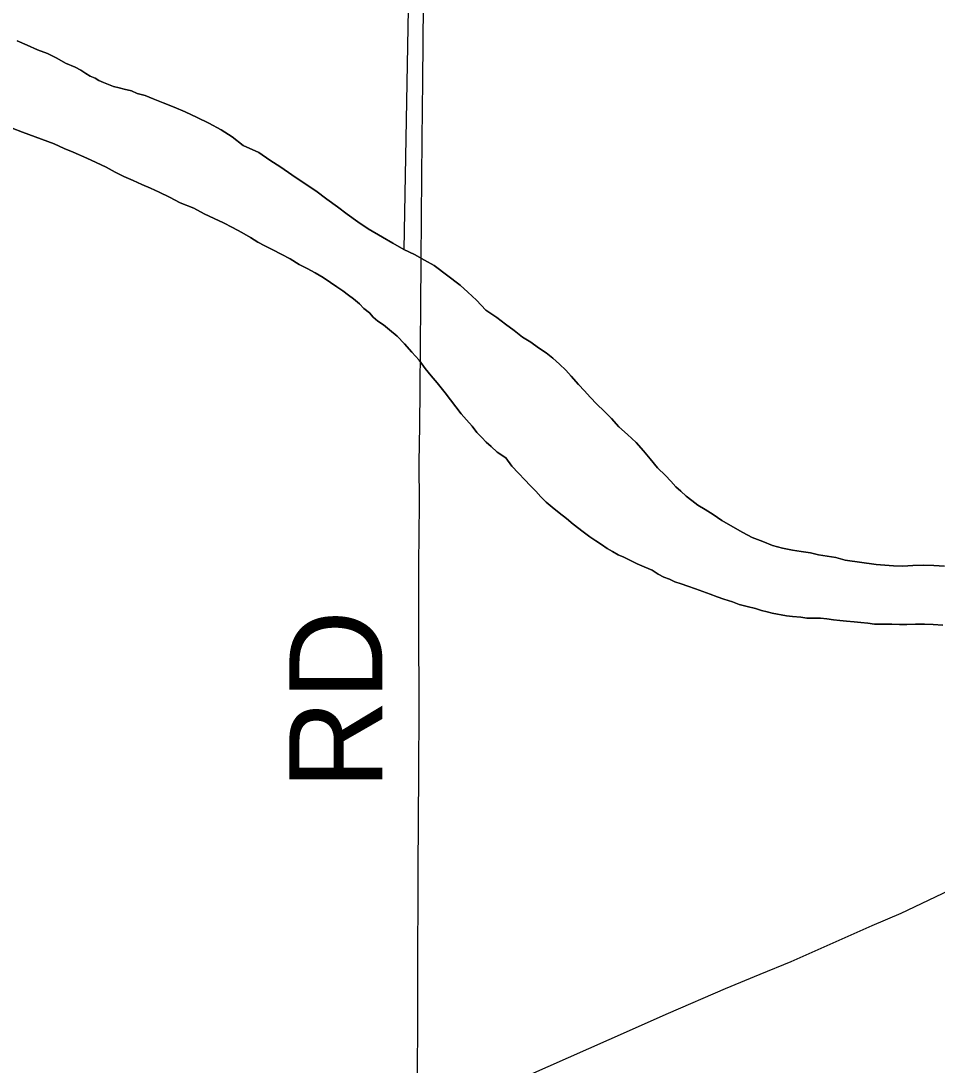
# Model space of a CAD drawing. Extents: x 2.1 to 73.9, y 4 to 26.
# Drawn here: x 45.0013 to 45.2814, y 22.3847 to 22.704 of the extents above; entities that cross this region are included whole.
import ezdxf

# ---------------------------------------------------------------- set-up
doc = ezdxf.new("R2010")
doc.units = 0
for name, color, linetype in [('GM_X_County_Road', 7, 'Continuous'), ('GM_X_County_Road_Text', 7, 'Continuous'), ('GM_X_Major_River', 7, 'Continuous'), ('GM_X_Minor_River', 7, 'Continuous')]:
    doc.layers.add(name, color=color, linetype=linetype)

msp = doc.modelspace()

# ---------------------------------------------------------------- linework, layer by layer
at = {"layer": 'GM_X_County_Road'}
for points in [[(45.12254, 22.36637), (45.12257, 22.36972), (45.12266, 22.41012), (45.12276, 22.44462), (45.12295, 22.47415), (45.12307, 22.49373), (45.12298, 22.51953), (45.12296, 22.53787), (45.12316, 22.5562), (45.12312, 22.56894), (45.12326, 22.58012), (45.12335, 22.59132), (45.12354, 22.61742), (45.12367, 22.63016), (45.12376, 22.64415), (45.12398, 22.66788), (45.12418, 22.6858), (45.1246, 22.73211), (45.12482, 22.75884), (45.12528, 22.79614), (45.12563, 22.81936), (45.12577, 22.84028), (45.12584, 22.84534)], [(45.12254, 22.36637), (45.13764, 22.37322), (45.18113, 22.39248), (45.19932, 22.40055), (45.21674, 22.40804), (45.22738, 22.41243), (45.23683, 22.41638), (45.26157, 22.42732), (45.2704, 22.43114), (45.28304, 22.43711), (45.29225, 22.44163), (45.2967, 22.44381), (45.29941, 22.44531), (45.30667, 22.4495), (45.31849, 22.45638), (45.342, 22.47034), (45.35388, 22.47773), (45.36963, 22.48713), (45.37259, 22.48891)]]:
    msp.add_lwpolyline(points, dxfattribs=at)
at = {"layer": 'GM_X_Major_River'}
for points in [[(45.01228, 22.69262), (45.00945, 22.69399), (45.00642, 22.69518), (45.00321, 22.69656), (45.00019, 22.69794)], [(45.00019, 22.69794), (45.00321, 22.69656), (45.00642, 22.69518), (45.00945, 22.69399), (45.01228, 22.69262)], [(45.28371, 22.53726), (45.28048, 22.5375), (45.27724, 22.53755), (45.27401, 22.53741), (45.27096, 22.53727), (45.26811, 22.53731), (45.26545, 22.53755), (45.26279, 22.53778), (45.25331, 22.53907), (45.25047, 22.53987), (45.24781, 22.5403), (45.24515, 22.54072), (45.24269, 22.54133), (45.23984, 22.54175), (45.23719, 22.54217), (45.23416, 22.54279), (45.23112, 22.5436), (45.2281, 22.54479), (45.22489, 22.54598), (45.22206, 22.54755), (45.21829, 22.5497), (45.21565, 22.55126), (45.21301, 22.55301), (45.21057, 22.55457), (45.20831, 22.55593), (45.20643, 22.55729), (45.20474, 22.55865), (45.20305, 22.5602), (45.20155, 22.56155), (45.20005, 22.56328), (45.19837, 22.56502), (45.19593, 22.56734), (45.19369, 22.57004), (45.19164, 22.57254), (45.1894, 22.57504), (45.18677, 22.57756), (45.18415, 22.57988), (45.18191, 22.58238), (45.17966, 22.5847), (45.17741, 22.58683), (45.17535, 22.58895), (45.17367, 22.59087), (45.1718, 22.5928), (45.16956, 22.59531), (45.16787, 22.59724), (45.166, 22.59898), (45.16394, 22.60091), (45.16187, 22.60246), (45.15961, 22.60402), (45.15717, 22.60577), (45.15472, 22.60733), (45.15209, 22.60927), (45.14946, 22.61121), (45.14683, 22.61334), (45.14344, 22.61549), (45.14063, 22.61857), (45.13801, 22.62108), (45.13557, 22.62321), (45.12768, 22.62923), (45.12466, 22.63079), (45.12164, 22.63255), (45.11844, 22.63412), (45.11504, 22.63608), (45.11184, 22.63784), (45.1075, 22.64038), (45.1043, 22.64252), (45.10111, 22.64485), (45.0981, 22.64718), (45.0949, 22.64951), (45.09152, 22.65203), (45.08794, 22.65437), (45.08418, 22.6569), (45.08079, 22.65923), (45.0774, 22.66137), (45.07402, 22.66371), (45.0693, 22.66587), (45.06592, 22.66859), (45.06253, 22.67073), (45.05875, 22.67269), (45.05517, 22.67446), (45.05158, 22.67623), (45.04818, 22.67761), (45.04478, 22.67899), (45.04175, 22.68018), (45.0393, 22.68117), (45.03683, 22.68178), (45.03513, 22.68257), (45.03286, 22.68317), (45.03135, 22.68358), (45.02964, 22.68398), (45.02813, 22.68458), (45.02662, 22.68517), (45.0251, 22.68577), (45.02398, 22.68654), (45.02246, 22.68714), (45.02114, 22.68792), (45.01964, 22.68889), (45.01794, 22.68987), (45.01492, 22.69106), (45.01228, 22.69262)], [(45.01228, 22.69262), (45.01492, 22.69106), (45.01794, 22.68987), (45.01964, 22.68889), (45.02114, 22.68792), (45.02246, 22.68714), (45.02398, 22.68654), (45.0251, 22.68577), (45.02662, 22.68517), (45.02813, 22.68458), (45.02964, 22.68398), (45.03135, 22.68358), (45.03286, 22.68317), (45.03513, 22.68257), (45.03683, 22.68178), (45.0393, 22.68117), (45.04175, 22.68018), (45.04478, 22.67899), (45.04818, 22.67761), (45.05158, 22.67623), (45.05517, 22.67446), (45.05875, 22.67269), (45.06253, 22.67073), (45.06592, 22.66859), (45.0693, 22.66587), (45.07402, 22.66371), (45.0774, 22.66137), (45.08079, 22.65923), (45.08418, 22.6569), (45.08794, 22.65437), (45.09152, 22.65203), (45.0949, 22.64951), (45.0981, 22.64718), (45.10111, 22.64485), (45.1043, 22.64252), (45.1075, 22.64038), (45.11184, 22.63784), (45.11504, 22.63608), (45.11844, 22.63412), (45.12164, 22.63255), (45.12466, 22.63079), (45.12768, 22.62923), (45.13557, 22.62321), (45.13801, 22.62108), (45.14063, 22.61857), (45.14344, 22.61549), (45.14683, 22.61334), (45.14946, 22.61121), (45.15209, 22.60927), (45.15472, 22.60733), (45.15717, 22.60577), (45.15961, 22.60402), (45.16187, 22.60246), (45.16394, 22.60091), (45.166, 22.59898), (45.16787, 22.59724), (45.16956, 22.59531), (45.1718, 22.5928), (45.17367, 22.59087), (45.17535, 22.58895), (45.17741, 22.58683), (45.17966, 22.5847), (45.18191, 22.58238), (45.18415, 22.57988), (45.18677, 22.57756), (45.1894, 22.57504), (45.19164, 22.57254), (45.19369, 22.57004), (45.19593, 22.56734), (45.19837, 22.56502), (45.20005, 22.56328), (45.20155, 22.56155), (45.20305, 22.5602), (45.20474, 22.55865), (45.20643, 22.55729), (45.20831, 22.55593), (45.21057, 22.55457), (45.21301, 22.55301), (45.21565, 22.55126), (45.21829, 22.5497), (45.22206, 22.54755), (45.22489, 22.54598), (45.2281, 22.54479), (45.23112, 22.5436), (45.23416, 22.54279), (45.23719, 22.54217), (45.23984, 22.54175), (45.24269, 22.54133), (45.24515, 22.54072), (45.24781, 22.5403), (45.25047, 22.53987), (45.25331, 22.53907), (45.26279, 22.53778), (45.26545, 22.53755), (45.26811, 22.53731), (45.27096, 22.53727), (45.27401, 22.53741), (45.27724, 22.53755), (45.28048, 22.5375), (45.28371, 22.53726)], [(44.99863, 22.67118), (45.00184, 22.66998), (45.01149, 22.66641), (45.01451, 22.66503), (45.01734, 22.66385), (45.0215, 22.66207), (45.02433, 22.6607), (45.02735, 22.65932), (45.03018, 22.65775), (45.03282, 22.65638), (45.03566, 22.6552), (45.0383, 22.65402), (45.04094, 22.65283), (45.04359, 22.65165), (45.0468, 22.65008), (45.05, 22.64832), (45.05416, 22.64673), (45.05737, 22.64497), (45.06039, 22.64359), (45.06322, 22.64222), (45.06605, 22.64084), (45.06888, 22.63928), (45.07152, 22.63772), (45.07378, 22.63635), (45.07585, 22.63518), (45.0783, 22.634), (45.08094, 22.63263), (45.08359, 22.63126), (45.08641, 22.6295), (45.08887, 22.62832), (45.09132, 22.62695), (45.09377, 22.62558), (45.09602, 22.62403), (45.09791, 22.62267), (45.09979, 22.6215), (45.10148, 22.62014), (45.10298, 22.61898), (45.10486, 22.61743), (45.10617, 22.61608), (45.10786, 22.61472), (45.10898, 22.61337), (45.11048, 22.61221), (45.11218, 22.61104), (45.11405, 22.60949), (45.11631, 22.60755), (45.11855, 22.60524), (45.12079, 22.60273), (45.12304, 22.60023), (45.1249, 22.59773), (45.12677, 22.59542), (45.12863, 22.5933)], [(45.12863, 22.5933), (45.12677, 22.59542), (45.1249, 22.59773), (45.12304, 22.60023), (45.12079, 22.60273), (45.11855, 22.60524), (45.11631, 22.60755), (45.11405, 22.60949), (45.11218, 22.61104), (45.11048, 22.61221), (45.10898, 22.61337), (45.10786, 22.61472), (45.10617, 22.61608), (45.10486, 22.61743), (45.10298, 22.61898), (45.10148, 22.62014), (45.09979, 22.6215), (45.09791, 22.62267), (45.09602, 22.62403), (45.09377, 22.62558), (45.09132, 22.62695), (45.08887, 22.62832), (45.08641, 22.6295), (45.08359, 22.63126), (45.08094, 22.63263), (45.0783, 22.634), (45.07585, 22.63518), (45.07378, 22.63635), (45.07152, 22.63772), (45.06888, 22.63928), (45.06605, 22.64084), (45.06322, 22.64222), (45.06039, 22.64359), (45.05737, 22.64497), (45.05416, 22.64673), (45.05, 22.64832), (45.0468, 22.65008), (45.04359, 22.65165), (45.04094, 22.65283), (45.0383, 22.65402), (45.03566, 22.6552), (45.03282, 22.65638), (45.03018, 22.65775), (45.02735, 22.65932), (45.02433, 22.6607), (45.0215, 22.66207), (45.01734, 22.66385), (45.01451, 22.66503), (45.01149, 22.66641), (45.00184, 22.66998), (44.99863, 22.67118)], [(45.12863, 22.5933), (45.13106, 22.59022), (45.1359, 22.58387), (45.13758, 22.58195), (45.13927, 22.58002), (45.14076, 22.5781), (45.14225, 22.57655), (45.14357, 22.5752), (45.14507, 22.57385), (45.14694, 22.57211), (45.14957, 22.57036), (45.15144, 22.56786), (45.1535, 22.56573), (45.15536, 22.56361), (45.15705, 22.56188), (45.15873, 22.56014), (45.16023, 22.55841), (45.16192, 22.55686), (45.16379, 22.55531), (45.16586, 22.55357), (45.16811, 22.55182), (45.17018, 22.55008), (45.17318, 22.54775), (45.17525, 22.5462), (45.17713, 22.54503), (45.17883, 22.54386), (45.18052, 22.54269), (45.18222, 22.54172), (45.18391, 22.54074), (45.18561, 22.53995), (45.18769, 22.53897), (45.18977, 22.53799), (45.19184, 22.537), (45.1943, 22.53602), (45.19618, 22.53484), (45.19788, 22.53387), (45.19958, 22.53327), (45.20128, 22.53248), (45.20317, 22.53188), (45.20525, 22.53109), (45.20752, 22.5303), (45.20979, 22.5295), (45.21206, 22.5287), (45.21414, 22.52791), (45.21622, 22.52712), (45.21887, 22.52632), (45.22095, 22.52552), (45.22341, 22.52491), (45.22588, 22.5243), (45.22777, 22.5237), (45.22948, 22.5233), (45.23099, 22.52289), (45.23535, 22.52206), (45.23725, 22.52184), (45.23972, 22.52161), (45.24162, 22.52139), (45.24352, 22.52136), (45.2458, 22.52133), (45.2477, 22.52111), (45.24979, 22.52088), (45.25168, 22.52066), (45.25377, 22.52044), (45.25605, 22.52021), (45.25814, 22.51999), (45.26023, 22.51977), (45.26232, 22.51955), (45.26536, 22.5195), (45.26764, 22.51946), (45.26992, 22.51942), (45.27221, 22.51939), (45.27487, 22.51954), (45.27753, 22.51949), (45.28019, 22.51945), (45.28323, 22.51921)], [(45.28323, 22.51921), (45.28019, 22.51945), (45.27753, 22.51949), (45.27487, 22.51954), (45.27221, 22.51939), (45.26992, 22.51942), (45.26764, 22.51946), (45.26536, 22.5195), (45.26232, 22.51955), (45.26023, 22.51977), (45.25814, 22.51999), (45.25605, 22.52021), (45.25377, 22.52044), (45.25168, 22.52066), (45.24979, 22.52088), (45.2477, 22.52111), (45.2458, 22.52133), (45.24352, 22.52136), (45.24162, 22.52139), (45.23972, 22.52161), (45.23725, 22.52184), (45.23535, 22.52206), (45.23099, 22.52289), (45.22948, 22.5233), (45.22777, 22.5237), (45.22588, 22.5243), (45.22341, 22.52491), (45.22095, 22.52552), (45.21887, 22.52632), (45.21622, 22.52712), (45.21414, 22.52791), (45.21206, 22.5287), (45.20979, 22.5295), (45.20752, 22.5303), (45.20525, 22.53109), (45.20317, 22.53188), (45.20128, 22.53248), (45.19958, 22.53327), (45.19788, 22.53387), (45.19618, 22.53484), (45.1943, 22.53602), (45.19184, 22.537), (45.18977, 22.53799), (45.18769, 22.53897), (45.18561, 22.53995), (45.18391, 22.54074), (45.18222, 22.54172), (45.18052, 22.54269), (45.17883, 22.54386), (45.17713, 22.54503), (45.17525, 22.5462), (45.17318, 22.54775), (45.17018, 22.55008), (45.16811, 22.55182), (45.16586, 22.55357), (45.16379, 22.55531), (45.16192, 22.55686), (45.16023, 22.55841), (45.15873, 22.56014), (45.15705, 22.56188), (45.15536, 22.56361), (45.1535, 22.56573), (45.15144, 22.56786), (45.14957, 22.57036), (45.14694, 22.57211), (45.14507, 22.57385), (45.14357, 22.5752), (45.14225, 22.57655), (45.14076, 22.5781), (45.13927, 22.58002), (45.13758, 22.58195), (45.1359, 22.58387), (45.13106, 22.59022), (45.12863, 22.5933)]]:
    msp.add_lwpolyline(points, dxfattribs=at)
at = {"layer": 'GM_X_Minor_River'}
msp.add_lwpolyline([(45.12168, 22.81523), (45.11844, 22.63412)], dxfattribs=at)

# ---------------------------------------------------------------- texts
at = {"layer": 'GM_X_County_Road_Text'}
msp.add_text('RD', height=0.028409, rotation=90, dxfattribs=at).set_placement((45.11181, 22.46893))

doc.saveas('drawing.dxf')
